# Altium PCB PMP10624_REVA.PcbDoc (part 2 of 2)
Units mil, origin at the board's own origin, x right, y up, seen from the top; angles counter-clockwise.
Board outline 2850 x 2600 mil, 4 copper layers (Top Layer, Signal Layer 1, Signal Layer 2, Bottom Layer), stack 61.2 mil thick; 108 components, 51 nets, 253 pads, 67 vias.
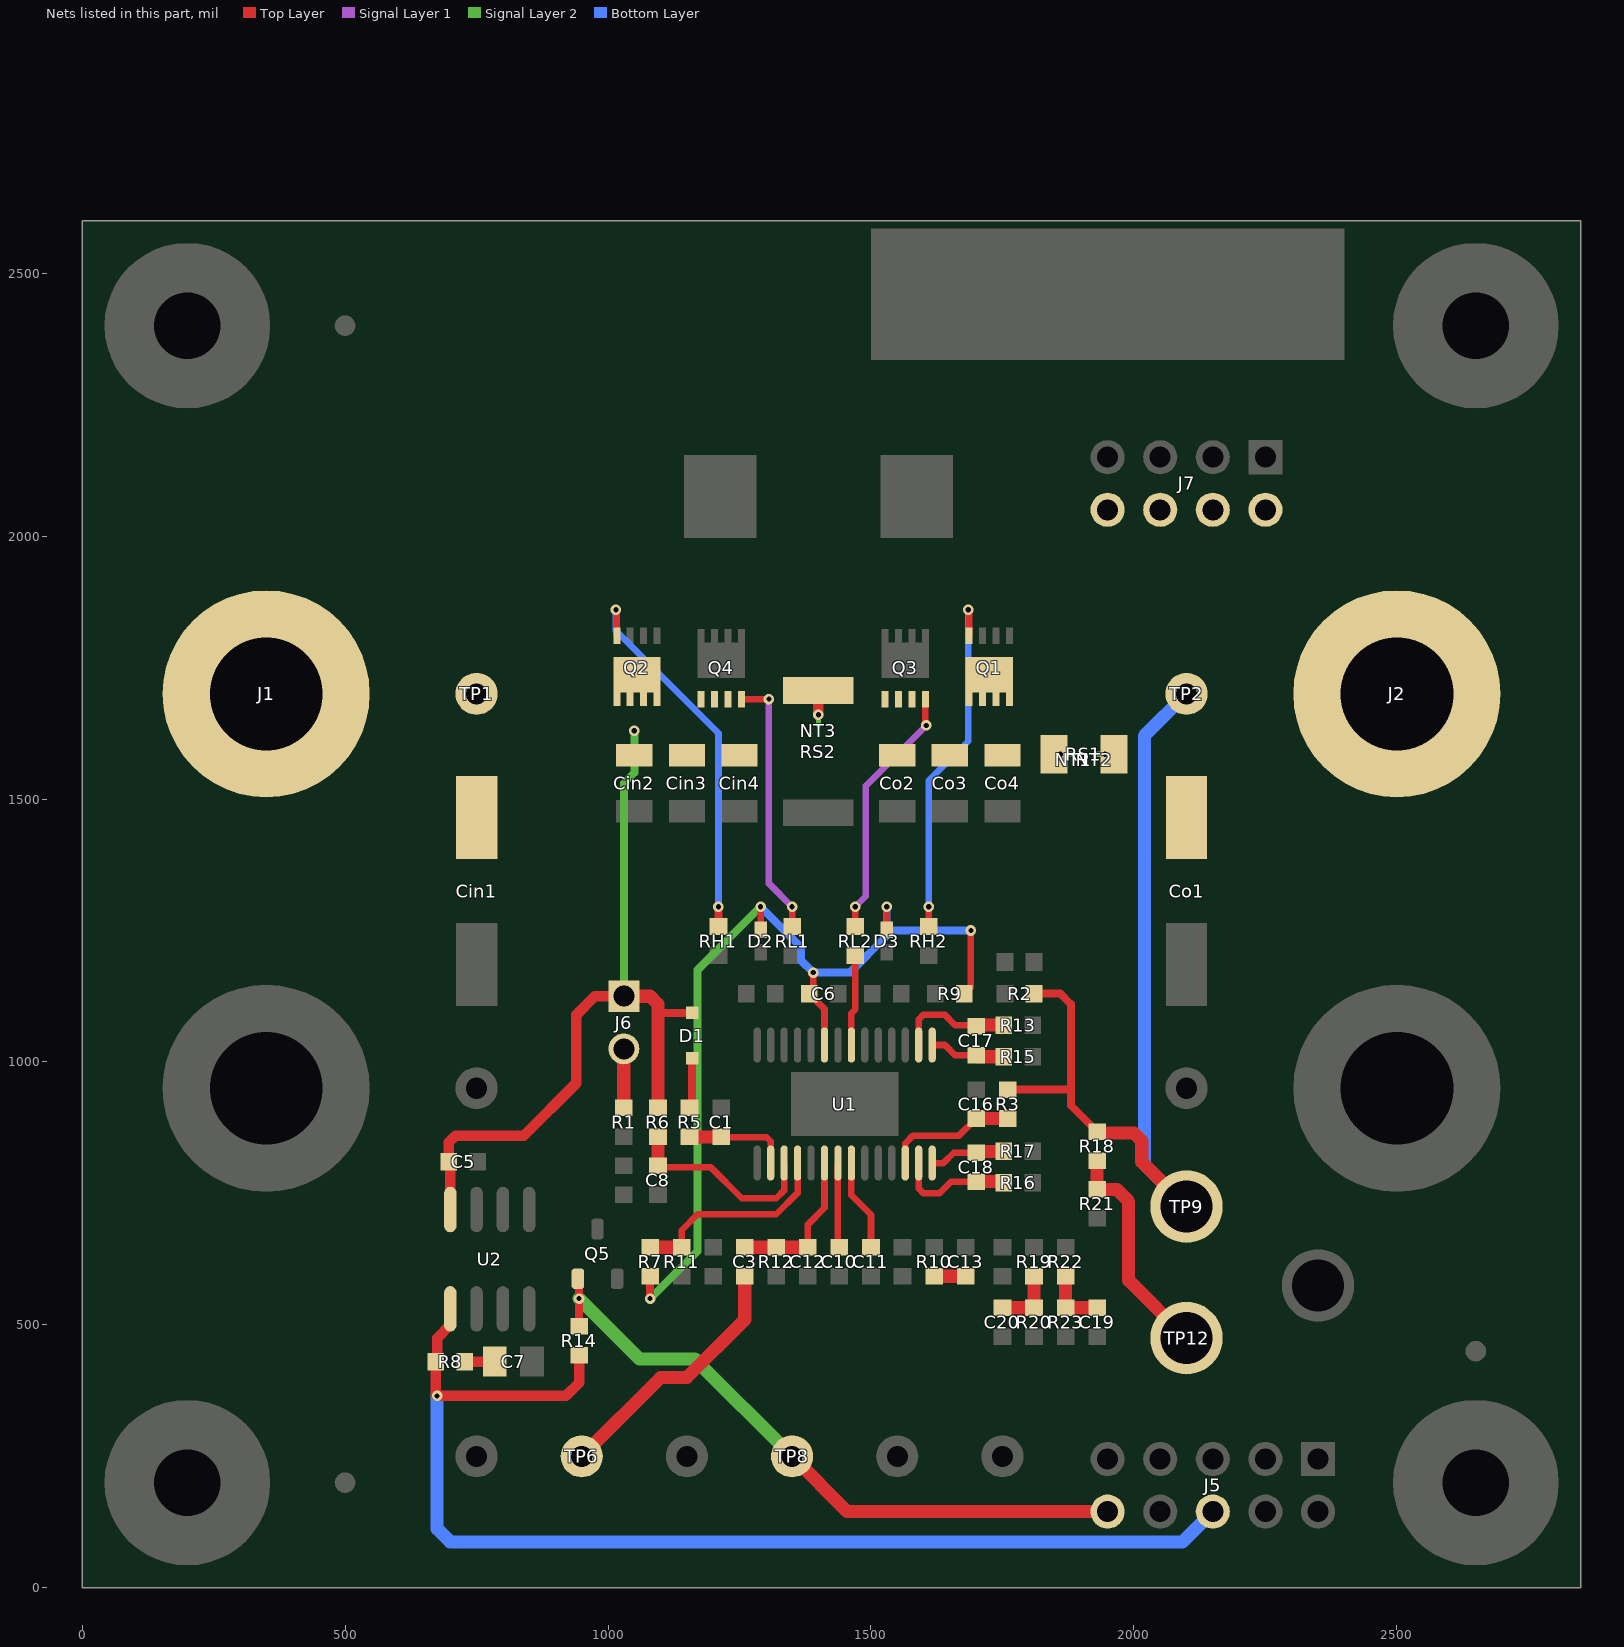
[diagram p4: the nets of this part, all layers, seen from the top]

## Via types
v1: diameter 20, hole 10, Top Layer to Bottom Layer, 59 vias
v2: diameter 40, hole 20, Top Layer to Bottom Layer, 8 vias

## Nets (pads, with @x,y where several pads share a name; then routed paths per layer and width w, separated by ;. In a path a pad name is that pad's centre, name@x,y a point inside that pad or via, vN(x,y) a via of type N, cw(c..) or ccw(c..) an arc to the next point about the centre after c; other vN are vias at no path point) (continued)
LDRV2: RL2.2 U1.21 | length 172.7
  Top Layer w12.5: U1.21@1462.8,1032.2 1462.8,1092.8 1470,1100 RL2.2@1470,1201.95
MODE: R7.1 R11.2 U1.4 | length 399.2
  Top Layer w12.5: R11.2@1140,647.56 1140,680 1170.37,710.37 1320,710.37 1360.43,750.81 U1.4@1360.43,807.8
  Top Layer w25: R7.1@1080,647.56 R11.2@1140,647.56
NetC3_1: C3.1 TP6.1 | length 500.1
  Top Layer w25: TP6.1@950,250 1100,400 1150,400 1260,510 C3.1@1260,592.44
NetC7_1: C7.1 R8.1 | length 57
  Top Layer w20: R8.1@727.56,430 C7.1@784.57,430
NetC13_1: C13.1 R10.1 | length 60
  Top Layer w25: R10.1@1620,592.44 C13.1@1680,592.44
NetC17_1: C17.1 R13.1 U1.16 | length 220.9
  Top Layer w12.5: U1.16@1590.75,1032.2 1590.75,1080.75 1600,1090 1640,1090 1660,1070 1697.56,1070 C17.1@1700,1067.56
  Top Layer w25: C17.1@1702.44,1070 R13.1@1752.44,1070
NetC17_2: C17.2 R15.1 U1.15 | length 145.3
  Top Layer w12.5: U1.15@1616.34,1032.2 1640.55,1032.2 1660.31,1012.44 C17.2@1700,1012.44
  Top Layer w25: C17.2@1700,1012.44 1702.44,1010 R15.1@1752.44,1010
NetC18_1: C18.1 R16.2 U1.13 | length 220.9
  Top Layer w12.5: U1.13@1590.75,807.8 1590.75,759.25 1600,750 1630,750 1652.44,772.44 C18.1@1700,772.44
  Top Layer w25: C18.1@1700,772.44 R16.2@1750,772.44
NetC18_2: C18.2 R17.2 U1.14 | length 145.3
  Top Layer w12.5: U1.14@1616.34,807.8 1637.8,807.8 1657.56,827.56 C18.2@1700,827.56
  Top Layer w25: C18.2@1700,827.56 1702.44,830 R17.2@1752.44,830
NetC19_1: C19.1 R22.1 R23.2 | length 119.9
  Top Layer w25: R22.1@1870,592.44 R23.2@1870,532.56 C19.1@1930,532.56
NetC20_1: C20.1 R19.1 R20.2 | length 119.9
  Top Layer w25: C20.1@1750,532.56 R20.2@1810,532.56 R19.1@1810,592.44
NetD1_1: D1.1 R5.2 | length 96.2
  Top Layer w15: R5.2@1155,912.56 1160,917.56 D1.1@1160,1006.69
NetJ6_2: J6.2 R1.2 | length 112.4
  Top Layer w25: R1.2@1030,912.56 J6.2@1030,1025
NetQ1_4: Q1.4 RH2.1 | length 683.6
  Top Layer w12.5: RH2.1@1610,1257.56 v1(1610,1295) ; v1(1685,1860) 1686.61,1858.39 Q1.4@1686.61,1810.53
  Bottom Layer w12.5: v1(1610,1295) 1610,1535 1685,1610 v1(1685,1860)
NetQ2_4: Q2.4 RH1.2 | length 733.3
  Top Layer w12.5: v1(1015,1860) 1016.61,1858.39 Q2.4@1016.61,1810.53
  Top Layer w15: RH1.2@1210,1257.56 v1(1210,1295)
  Bottom Layer w12.5: v1(1015,1860) 1015,1820 1210,1625 v1(1210,1295)
NetQ3_4: Q3.4 RL2.1 | length 488.5
  Top Layer w12.5: RL2.1@1470,1257.56 v1(1470,1295) ; Q3.4@1603.39,1689.47 1603.39,1641.61 v1(1605,1640)
  Signal Layer 1 w12.5: v1(1470,1295) 1490,1315 1490,1525 v1(1605,1640)
NetQ4_4: Q4.4 RL1.2 | length 503.4
  Top Layer w12.5: Q4.4@1253.39,1689.47 1305.33,1689.47 v1(1305.87,1690) ; RL1.2@1350,1257.56 v1(1350,1295)
  Signal Layer 1 w12.5: v1(1305.87,1690) 1305.87,1339.13 v1(1350,1295)
NetR18_2: R18.2 R21.2 TP12.1 | length 429.8
  Top Layer w25: R18.2@1930,812.44 R21.2@1930,757.56 1967.44,757.56 1990,735 1990,585 TP12.1@2100,475
SLOPE: C10.1 U1.7 | length 171.4
  Top Layer w12.5: C10.1@1437.2,640.35 U1.7@1437.2,807.8 ; C10.1@1437.2,650.35 C10.1@1440,647.56
SS: C11.1 U1.8 | length 175.6
  Top Layer w12.5: U1.8@1462.8,807.8 1462.8,746.68 1500,709.47 C11.1@1500,647.56
SYNC: C3.2 C12.2 R12.2 U1.6 | length 293.3
  Top Layer w12.5: C12.2@1380,647.56 1380,691.02 1411.61,722.64 U1.6@1411.61,807.8
  Top Layer w25: C3.2@1260,647.56 R12.2@1320,647.56 C12.2@1380,647.56
UFPBAR: J5.10 Q5.1 R14.1 TP8.1 | length 1260.6
  Top Layer w15: R14.1@945,497.56 v1(945,550) Q5.1@945,585.35
  Top Layer w25: TP8.1@1350,250 1455,145 J5.10@1950,145
  Signal Layer 2 w25: v1(945,550) 1060,435 1165,435 TP8.1@1350,250
VCC: C6.1 D2.2 D3.2 R7.2 R9.2 U1.23 | length 1784.7
  Top Layer w12.5: D2.2@1290,1251.65 v1(1290,1295) ; v1(1390,1170) 1390,1137.56 C6.1@1382.44,1130 1411.61,1100.83 U1.23@1411.61,1032.2 ; D3.2@1530,1251.65 v1@1530,1290 ; R9.2@1677.56,1130 1690,1142.44 v1(1690,1250)
  Top Layer w15: v1(1080,550) R7.2@1080,592.44
  Signal Layer 2 w15: v1(1080,550) 1170,640 1170,1175 v1(1290,1295)
  Bottom Layer w15: v1(1290,1295) 1366.85,1218.15 1366.85,1193.15 v1(1390,1170) 1460,1170 1530,1240 1530,1250 ; v1(1530,1295) 1530,1250 ; v1(1690,1250) 1530,1250
VDD: J5.6 R8.2 R14.2 U2.1 | length 2272.5
  Top Layer w20: U2.1@700,530.51 700,500 675,475 675,432.56 R8.2@672.44,430 672.44,367.56 v1(675,365) 920,365 945,390 R14.2@945,442.44
  Bottom Layer w25: v1(675,365) 675,112.5 700,87.5 2092.5,87.5 J5.6@2150,145
VIN: C5.1 Cin1.1 Cin2.1 Cin3.1 Cin4.1 D1.2 J1.1 J6.1 Q2.5 Q2.6 Q2.7 Q2.8 Q2.9 R6.1 TP1.1 U2.8 | length 1500.3
  Top Layer w15: 1095,1095 1096.69,1093.31 D1.2@1160,1093.31
  Top Layer w20: U2.8@700,719.49 700,807.44 C5.1@697.44,810 697.44,847.44 710,860 840,860 940,960 940,1090 975,1125 J6.1@1030,1125
  Top Layer w25: J6.1@1030,1125 1080,1125 1095,1110 1095,1095 R6.1@1095,912.56
  Signal Layer 2 w15: J6.1@1030,1125 1030,1530 1050,1550 v1(1050,1630)
VIN_IC: C1.1 R5.1 U1.2 | length 199.1
  Top Layer w12.5: C1.1@1215,857.44 1215.43,857.01 1301.5,857.01 1309.25,849.25 U1.2@1309.25,807.8
  Top Layer w25: R5.1@1155,857.44 C1.1@1215,857.44
VINSNS: C8.2 R6.2 U1.3 | length 378.7
  Top Layer w12.5: C8.2@1095,802.56 1097.56,800 1195,800 1254.25,740.75 1320,740.75 1334.84,755.59 U1.3@1334.84,807.8
  Top Layer w25: C8.2@1095,802.56 R6.2@1095,857.44
VOSNS: C16.1 R3.1 U1.12 | length 251.8
  Top Layer w12.5: U1.12@1565.16,807.8 1565.16,845.16 1580,860 1667.56,860 C16.1@1700,892.44
  Top Layer w25: C16.1@1700,892.44 R3.1@1760,892.44
VOUT: Co1.1 J2.1 J7.2 J7.4 J7.6 J7.8 NT2.2 R2.2 R3.2 R18.1 RS1.2 TP2.1 TP9.1 | length 1776.2
  Top Layer w15: R3.2@1760,947.56 1877.56,947.56 1880,950 ; R2.2@1810,1130 1860,1130 1880,1110 1880,950 ; R18.1@1930,867.56 1880,917.56 1880,950
  Top Layer w25: R18.1@1930,867.56 1932.56,865 2000,865 2015,850 2015,810 TP9.1@2100,725
  Signal Layer 2 w10: NT2.2@1925,1585 v1(1945,1585)
  Bottom Layer w25: TP9.1@2100,725 2020,805 2020,1620 TP2.1@2100,1700
VOUTC: Co2.1 Co3.1 Co4.1 NT1.2 Q1.5 Q1.6 Q1.7 Q1.8 Q1.9 RS1.1 | length 25
  Signal Layer 2 w10: v1(1860,1585) NT1.2@1885,1585
VRS: NT3.1 Q3.1 Q3.2 Q3.3 Q4.1 Q4.2 Q4.3 RS2.2 | length 66.1
  Top Layer w20: v1(1400,1660) RS2.2@1400,1706.14
  Signal Layer 2 w10: NT3.1@1400,1640 v1(1400,1660)
pads on no net: FID1.1 FID2.1 FID3.1 H1.1 H2.1 H3.1 H4.1 Logo1.0 U2.4 U2.5

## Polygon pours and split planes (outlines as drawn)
GND on Signal Layer 2 "Signal Layer 2-GND" (solid, remove dead copper, pour order 50): 0,0 0,2600 2850,2600 2850,0
GND on Signal Layer 1 "Signal Layer 1-GND" (solid, remove dead copper, pour order 49): 0,0 0,2600 2850,2600 2850,0
VIN on Bottom Layer "Bottom Layer-VIN" (solid, remove dead copper, pour order 51): 0,2100 1100,2100 1100,1360 510,1360 0,1360
VOUT on Bottom Layer "Top Layer-VOUT" (solid, remove dead copper, pour order 52): 1910,1650 1910,2100 2850,2100 2850,1330 2000,1330 2000,1650
GND on Bottom Layer "Bottom Layer-GND" (solid, remove dead copper, pour order 54): 0,0 0,2600 2850,2600 2850,0
VOUT on Top Layer "Top Layer-VOUT" (solid, remove dead copper, pour order 44): 1910,1330 1910,2100 2850,2100 2850,1940 2850,1330
VOUTC on Top Layer "Top Layer-VOUTC" (solid, remove dead copper, pour order 43): 1480,1610 1650,1610 1650,1770 1900,1770 1900,1535 1480,1535
VIN on Top Layer "Top Layer-VIN" (solid, remove dead copper, pour order 40): 0,2100 1000,2100 1000,1770 1130,1770 1130,1610 1320,1610 1320,1535 1000,1535 900,1535 900,1330 0,1330
GND on Top Layer "Top Layer-GND" (solid, remove dead copper, pour order 48): 0,0 0,2600 2850,2600 2850,0
VRS on Top Layer "Top Layer-VRS" (solid, remove dead copper, pour order 11): 1235,1710 1235,1662.6 1325,1662.6 1325,1755 1475,1755 1475,1710 1585,1710 1585,1620 1140,1620 1140,1710
HDRV1_N on Top Layer "Top Layer-SW1" (solid, remove dead copper, pour order 13): 1035,1790 1035,2185 1310,2185 1310,1725 1140,1725 1140,1790
HDRV2_N on Top Layer "Top Layer-SW2" (solid, remove dead copper, pour order 15): 1490,1725 1490,2185 1800,2185 1800,1790 1705,1790 1705,1885 1640,1885 1640,1725 1500,1725

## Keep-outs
Keep-Out Layer:
  lines w10: 6390,-5 ccw(c6390,0) 6395,0 ; -5,0 ccw(c0,0) 0,-5 ; -5,0 ccw(c0,0) 0,-5 ; -5,0 -5,2600 ; -5,2600 cw(c0,2600) 0,2605 ; -5,2600 cw(c0,2600) 0,2605 ; 0,-5 2850,-5 ccw(c2850,0) 2855,0 2855,2600 ; 0,2605 2850,2605 ; 2850,2605 cw(c2850,2600) 2855,2600 ; 2850,2605 cw(c2850,2600) 2855,2600
  text ".Layer_Name" at 577,-858.49 h60

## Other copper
Top Layer:
  text ".CopyrightYear" at 165,415 h60
  text "TI" at 441,415 h60
  text "©" at 48,411.48 h105
  text ".Layer_Name" at 577,-858.49 h60
Bottom Layer:
  text ".VersionControl_RevNumber" at 2590,2660 h60
  text "SVN:" at 2850,2660 h60
  text "MADE IN U.S." at 1365,120 h60
  text "UL94V-0" at 1880,120 h60
  text ".Layer_Name" at 577,-858.49 h60

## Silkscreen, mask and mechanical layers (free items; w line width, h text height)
Top Overlay:
  text "LM5175 Buck/Boost" at 450,2490 h60
  text ".PRJ_Number" at 675,2365 h60
  text ".PCB_Rev" at 1215,2365 h60
  text ".Layer_Name" at 577,-858.49 h60
Bottom Overlay:
  text ".Layer_Name" at 577,-858.49 h60
Top Paste:
  text ".Layer_Name" at 577,-858.49 h60
Bottom Paste:
  text ".Layer_Name" at 577,-858.49 h60
Top Solder:
  text ".Layer_Name" at 577,-858.49 h60
  text ".Layer_Name" at 577,-858.49 h60
Bottom Solder:
  text ".Layer_Name" at 577,-858.49 h60
Drill Guide:
  text ".Layer_Name" at 577,-858.49 h60
M1 Board Outline:
  the board outline again, w10
  text ".Layer_Name" at 577,-858.49 h60
M2 Board Dimensions:
  rectangle: 0,-275 125,-150
  rectangle: 125,-400 500,-275
  lines w7: 0,-275 1000,-275 ; 125,-400 125,-150 ; 250,-400 250,-150 ; 500,-400 500,-150 ; 750,-400 750,-150 ; 0,-400 1000,-400 1000,-150 0,-150 0,-400
  text ".Layer_Name" at 577,-858.49 h60
M3 3D STEP Top:
  text ".Layer_Name" at 577,-858.49 h60
M4 3D STEP Bottom:
  text ".Layer_Name" at 577,-858.49 h60
M5 Assembly Top:
  lines w10: -292,-930.17 6308,-930.17 ; -292,-726.83 6310,-726.83 ; -292,-523.5 -292,-1133.5 3713,-1133.5 6310,-1133.5 6310,-523.5 -291.5,-523.5 -291.5,-1133.5 1284,-1133.5 ; 2173,-1133.5 2173,-523.5 ; 3440,-726.83 3440,-523.5 ; 4280,-726.83 4280,-523.5 ; 4902,-1140 4902,-937.17
  text "COMPONENTS MARKED 'DNP' SHOULD NOT BE POPULATED." at 1153.5,-318.5 h60
  text "ASSEMBLY VARIANT:" at 1153,-434 h60
  text ".VariantName" at 2189,-434 h60
  text "PCB VIEWED FROM TOP SIDE" at -228.5,-655.67 h60
  text "BOARD #:" at 2248,-655.67 h60
  text ".PRJ_Number" at 2793.5,-655.67 h60
  text "REV:" at 3638,-655.67 h60
  text ".PCB_Rev" at 3929.5,-655.67 h60
  text "SVN REV:" at 4476,-655.67 h60
  text ".VersionControl_RevNumber" at 4982,-655.67 h60
  text "PLOT NAME =" at -228.5,-1064.34 h60
  text ".plot_File_Name" at 577,-1064.34 h60
  text "GENERATED    :" at 2250,-1064.34 h60
  text ".Print_Date" at 3119.5,-1064.34 h60
  text ".Print_Time" at 3848.5,-1064.34 h60
  text "TEXAS INSTRUMENTS" at 5113,-1064.34 h60
M6 Assembly Bottom:
  lines w10: -292.5,-727.33 6309.5,-727.33 ; -290.5,-930.67 6309.5,-930.67 ; 1115.5,-1140.5 1115.5,-937.67 ; 1737.5,-727.33 1737.5,-524 ; 2577.5,-727.33 2577.5,-524 ; 3844.5,-1134 3844.5,-524 ; 4733.5,-1134 6309,-1134 6309,-524 -292.5,-524 -292.5,-1134 2304.5,-1134 6309.5,-1134 6309.5,-524
  text "COMPONENTS MARKED 'DNP' SHOULD NOT BE POPULATED." at 6102,-318 h60
  text ".VariantName" at 5058,-434 h60
  text "ASSEMBLY VARIANT:" at 6097,-434 h60
  text ".VersionControl_RevNumber" at 1035.5,-656.17 h60
  text "SVN REV:" at 1541.5,-656.17 h60
  text ".PCB_Rev" at 2088,-656.17 h60
  text "REV:" at 2379.5,-656.17 h60
  text ".PRJ_Number" at 3224,-656.17 h60
  text "BOARD #:" at 3769.5,-656.17 h60
  text "PCB VIEWED FROM BOTTOM SIDE" at 6246,-656.17 h60
  text "TEXAS INSTRUMENTS" at 904.5,-1064.84 h60
  text ".Print_Time" at 2169,-1064.84 h60
  text ".Print_Date" at 2898,-1064.84 h60
  text "GENERATED    :" at 3767.5,-1064.84 h60
  text ".plot_File_Name" at 5440.5,-1064.84 h60
  text "PLOT NAME =" at 6246,-1064.84 h60
M9 Title Sheet:
  drawing of 57 lines, arcs and shapes, not listed
  text "1" at 739.84,8036.5 h70
  text "2" at 3235.5,8036.5 h70
  text "3" at 5724.84,8036.5 h70
  text "4" at 8231.51,8036.5 h70
  text "5" at 10730.5,8036.5 h70
  text "6" at 13235.5,8036.5 h70
  text "A" at -416.5,6893.5 h70
  text "A" at 14383.5,6893.5 h70
  text "B" at -416.5,4513.5 h70
  text "B" at 14383.5,4513.5 h70
  text "C" at -416.5,2138.5 h70
  text "C" at 14383.5,2138.5 h70
  text "PROJECT TITLE:" at 11343.5,277.5 h45
  text ".PRJ_Title" at 11393.5,144.17 h70
  text "DESIGNED FOR:" at 11343.5,-23.5 h45
  text ".PRJ_Customer" at 11393.5,-163.5 h70
  text "D" at -416.5,-231.5 h70
  text "D" at 14383.5,-231.5 h70
  text "FILE NAME:" at 11343.5,-323.5 h45
  text ".PCB_File_Name_No_Path" at 11393.5,-443.5 h70
  text "Texas Instruments (TI) and/or its licensors do not warrant the accuracy or completeness of this specification" at 6374,-605.34 h45
  text "ENGINEER:" at 11343.5,-613.5 h45
  text "LAYOUT BY:" at 12848.5,-613.5 h45
  text "or any information contained therein. TI and/or its licensors do not warrant that this design will meet" at 6329.01,-718 h45
  text ".PRJ_Engineer" at 11393.5,-768.49 h70
  text ".PCB_Layout" at 12899,-768.49 h70
  text "the specifications, will be suitable for your application or fit for any particular purpose, or will operate in" at 6329.01,-830.67 h45
  text ".Layer_Name" at 577,-858.49 h60
  text "ALTIUM DESIGNER VERSION:" at 12848.5,-923.5 h45
  text "an implementation. TI and/or its licensors do not warrant that the design is production worthy. You should" at 6329.01,-943.33 h45
  text "completely validate and test your design implementation to confirm the system functionality for your application." at 6374,-1056 h45
  text ".print_Scale" at 11393.5,-1056.83 h70
  text ".Application_BuildNumber" at 12899,-1056.83 h70
  text "1" at 739.84,-1263.5 h70
  text "2" at 3235.5,-1263.5 h70
  text "3" at 5724.84,-1263.5 h70
  text "4" at 8231.51,-1263.5 h70
  text "5" at 10730.5,-1263.5 h70
  text "6" at 13235.5,-1263.5 h70
M10 Fab Notes:
  drawing of 185 lines, arcs and shapes, not listed
  text "DESIGN INFORMATION" at 12381.02,5910 h60
  text "MIN. TRACK WIDTH:" at 11736.46,5730 h60
  text "7.8" at 12775,5730 h60
  text "MIL" at 12987.46,5730 h60
  text "MIN. CLEARANCE:" at 11736.46,5598 h60
  text "0.2" at 12772.7,5598 h60
  text "mm" at 12987.46,5598 h60
  text "MIN. VIA PAD SIZE:" at 11736.46,5466 h60
  text "20" at 12802.71,5466 h60
  text "MIL" at 12987.46,5466 h60
  text "0.05mm (2MIL)" at 12431.46,5324.29 h60
  text "MINIMUM ANNULAR RING" at 11407.23,5320 h60
  text "EXTERNAL" at 13139.46,5320 h60
  text "PER" at 11607.23,5202 h60
  text "IPC-D-275 CLASS 2 LEVEL C" at 11827.23,5202 h60
  text "MIL, HOLES" at 13315.46,5089.71 h60
  text "+/-" at 12923,5089 h60
  text "+/-" at 13777,5089 h60
  text "REGISTRATION TOLERANCES:" at 11407.23,5084 h60
  text "METAL" at 12607,5084 h60
  text "5" at 13183.2,5084 h60
  text "3" at 14016.2,5084 h60
  text "MIL" at 14132.46,5084 h60
  text "MATERIAL:" at 11332.46,4874.54 h60
  text "FR-4 High Tg" at 12318.9,4734.21 h60
  text "FR-408" at 11753.46,4725.64 h60
  text "OTHER" at 13241.46,4725.64 h60
  text "X" at 11600,4720 h60
  text "62 MIL (1.6mm) +/-10%" at 12073.56,4562.92 h60
  text "THICKNESS:" at 11407.23,4558.64 h60
  text "X" at 11945.4,4558.64 h60
  text "OTHER" at 13358.46,4558.64 h60
  text "TOLERANCE:" at 11407.23,4400.64 h60
  text "X" at 12246.53,4400.64 h60
  text "ANSI IPC-6012 TYPE 3 CLASS 2" at 12433.48,4400.64 h60
  text "OTHER +/-" at 12433.46,4244.64 h60
  text "BOW & TWIST:" at 11407.23,4087.64 h60
  text "X" at 12246.53,4087.64 h60
  text "ANSI IPC-6012 TYPE 3 CLASS 2" at 12433.48,4087.64 h60
  text "OTHER +/-" at 12433.46,3929.13 h60
  text "DRILLING:" at 11332.46,3790.64 h60
  text "REFERENCE:" at 11407.23,3673.64 h60
  text "X" at 12055.46,3673.64 h60
  text "AS SHOWN" at 12242.46,3673.64 h60
  text "X" at 12956.46,3673.64 h60
  text "NC_DRILL FILES" at 13093.46,3673.64 h60
  text "PTH MIN COPPER THICKNESS:" at 11407.23,3515.64 h60
  text "X" at 12757.46,3515.64 h60
  text "1MIL" at 12894.46,3515.64 h60
  text "OTHER" at 13391.46,3515.64 h60
  text "BOARD FINISH:" at 11332.46,3356.64 h60
  text "SILKSCREEN:" at 11487.68,3238.64 h60
  text "X" at 12436.46,3238.64 h60
  text "TOP" at 12562.46,3238.64 h60
  text "X" at 12946.46,3238.64 h60
  text "BOTTOM" at 13073.46,3238.64 h60
  text "SILKSCREEN COLOR:" at 11487.68,3071.64 h60
  text "X" at 12435.42,3071.64 h60
  text "WHITE" at 12562.46,3071.64 h60
  text "OTHER" at 13073.46,3071.64 h60
  text "SOLDER RESIST COLOR:" at 11487.68,2901.64 h60
  text "X" at 12055.42,2742.44 h60
  text "GREEN" at 12182.46,2742.44 h60
  text "BLUE" at 12773.46,2742.44 h60
  text "OTHER" at 13311.46,2742.44 h60
  text "IMMERSION GOLD (ENIG)" at 12393.46,2553.92 h60
  text "ENEPIG" at 13731,2550.64 h60
  text "SURFACE FINISH:" at 11332.46,2549.64 h60
  text "IMM. TIN/SILVER OR EQUIV" at 11662,2392.64 h60
  text "OTHER" at 13093.46,2392.64 h60
  text "X" at 11500,2385 h60
  text "ARRAY/PANEL:" at 11332.46,2213.64 h60
  text "X" at 12205,2210 h60
  text "CUT AND TRIM PER MECH LAYER 1" at 12393.46,2209.35 h60
  text "N.C. ROUTE" at 12393.46,2057.64 h60
  text "V. SCORE" at 13259.46,2057.64 h60
  text "CERTIFICATION:" at 11332.46,1920.64 h60
  text "MATERIALS AND WORKMANSHIP FOR ALL PCBS" at 12057.46,1920.64 h60
  text "TO MEET OR EXCEED THE REQUIREMENTS OF:" at 12057.46,1822.64 h60
  text "X" at 11683.96,1686.13 h60
  text "ANSI IPC-A-600F CLASS ->" at 11822.96,1686.13 h60
  text "X" at 13462.02,1686.13 h60
  text "2" at 13580.96,1686.14 h60
  text "1" at 13265.96,1684.64 h60
  text "3" at 13934.96,1684.64 h60
  text "X" at 11686.02,1526.64 h60
  text "UL 94V-0" at 11822.96,1526.64 h60
  text "X" at 12498.02,1526.64 h60
  text "RoHS" at 12634.96,1526.64 h60
  text "OTHER" at 13279.36,1526.64 h60
  text "PER ORDER" at 13676.42,1526.64 h60
  text "ADDITIONAL REQUIREMENTS:" at 11332.46,1385.64 h60
  text "MICROSECTION:" at 11407.23,1270.64 h60
  text "YES" at 12312.96,1270.64 h60
  text "REQUIRED" at 13174.46,1114.49 h60
  text "BARE BOARD ELEC. TEST:" at 11407.23,1111.64 h60
  text "NONE" at 12712.96,1111.64 h60
  text "PER ORDER" at 13766.46,1111.64 h60
  text "X" at 13640,1110 h60
  text "MANUFACTURER'S UL:" at 11407.23,954.64 h60
  text "RAIL" at 12572.96,950.35 h60
  text "METAL" at 13064.77,950.35 h60
  text "X" at 13440,950 h60
  text "SILK" at 13576.46,950.35 h60
  text ".Layer_Name" at 577,-858.49 h60
M11 Gerber Information:
  lines w10: -292,-930.17 6308,-930.17 ; -292,-726.83 6310,-726.83 ; -292,-523.5 -292,-1133.5 3713,-1133.5 6310,-1133.5 6310,-523.5 -291.5,-523.5 -291.5,-1133.5 1284,-1133.5 ; 2173,-1133.5 2173,-523.5 ; 3440,-726.83 3440,-523.5 ; 4280,-726.83 4280,-523.5 ; 4902,-1140 4902,-937.17
  text "ALL ARTWORK VIEWED FROM TOP SIDE" at -228.5,-655.67 h60
  text "BOARD #:" at 2248,-655.67 h60
  text ".PRJ_Number" at 2793.5,-655.67 h60
  text "REV:" at 3638,-655.67 h60
  text ".PCB_Rev" at 3929.5,-655.67 h60
  text "SVN REV:" at 4476,-655.67 h60
  text ".VersionControl_RevNumber" at 4982,-655.67 h60
  text "LAYER NAME =" at -228.5,-858.49 h60
  text "PLOT NAME =" at -228.5,-1064.34 h60
  text ".plot_File_Name" at 577,-1064.34 h60
  text "GENERATED    :" at 2250,-1064.34 h60
  text ".Print_Date" at 3119.5,-1064.34 h60
  text ".Print_Time" at 3848.5,-1064.34 h60
  text "TEXAS INSTRUMENTS" at 5113,-1064.34 h60
M12 Stackup:
  drawing of 295 lines, arcs and shapes, not listed
  text "Layer" at 9605.74,7700 h60
  text "Name" at 10015.66,7700 h60
  text "Material" at 10955.4,7700 h60
  text "Thickness" at 11815.16,7700 h60
  text "Constant" at 12465,7700 h60
  text "Board Layer Stack" at 13034.86,7700 h60
  text "1" at 9605.74,7580 h60
  text "Top Overlay" at 10015.66,7580 h60
  text "2" at 9605.74,7460 h60
  text "Top Solder" at 10015.66,7460 h60
  text "Solder Resist" at 10955.4,7460 h60
  text "0.40mil" at 11815.16,7460 h60
  text "3.5" at 12465,7460 h60
  text "3" at 9605.74,7340 h60
  text "Top Layer" at 10015.66,7340 h60
  text "Copper" at 10955.4,7340 h60
  text "2.80mil" at 11815.16,7340 h60
  text "4" at 9605.74,7220 h60
  text "Dielectric1" at 10015.66,7220 h60
  text "FR-4" at 10955.4,7220 h60
  text "20.00mil" at 11815.16,7220 h60
  text "4.8" at 12465,7220 h60
  text "5" at 9605.74,7100 h60
  text "Signal Layer 1" at 10015.66,7100 h60
  text "Copper" at 10955.4,7100 h60
  text "1.40mil" at 11815.16,7100 h60
  text "6" at 9605.74,6980 h60
  text "Dielectric 2" at 10015.66,6980 h60
  text "12.80mil" at 11815.16,6980 h60
  text "4.2" at 12465,6980 h60
  text "7" at 9605.74,6860 h60
  text "Signal Layer 2" at 10015.66,6860 h60
  text "Copper" at 10955.4,6860 h60
  text "1.40mil" at 11815.16,6860 h60
  text "8" at 9605.74,6740 h60
  text "Dielectric 3" at 10015.66,6740 h60
  text "FR-4" at 10955.4,6740 h60
  text "20.00mil" at 11815.16,6740 h60
  text "4.8" at 12465,6740 h60
  text "9" at 9605.74,6620 h60
  text "Bottom Layer" at 10015.66,6620 h60
  text "Copper" at 10955.4,6620 h60
  text "2.80mil" at 11815.16,6620 h60
  text "10" at 9605.74,6500 h60
  text "Bottom Solder" at 10015.66,6500 h60
  text "Solder Resist" at 10955.4,6500 h60
  text "0.40mil" at 11815.16,6500 h60
  text "3.5" at 12465,6500 h60
  text "11" at 9605.74,6380 h60
  text "Bottom Overlay" at 10015.66,6380 h60
  text ".Layer_Name" at 577,-858.49 h60
M13 Component Bodies Top:
  text ".Layer_Name" at 577,-858.49 h60
M14 Component Bodies Bottom:
  text ".Layer_Name" at 577,-858.49 h60
M15 Courtyards Top:
  text ".Layer_Name" at 577,-858.49 h60
M16 Courtyards Bottom:
  text ".Layer_Name" at 577,-858.49 h60
Drill Drawing:
  circle w3.33: c3592.72,1923.08 r24.89
  lines w3.33: 3567.83,1599.56 3617.6,1599.56 3617.6,1649.33 3567.83,1649.33 3567.83,1599.56 ; 3567.83,1748.88 3617.6,1748.88 3617.6,1798.65 3567.83,1798.65 3567.83,1748.88 ; 3567.83,2047.52 3592.72,2059.96 3617.6,2047.52 3605.16,2072.4 3617.6,2097.29 3592.72,2084.85 3567.83,2097.29 3580.27,2072.4 3567.83,2047.52 ; 3567.83,2246.61 3617.6,2246.61 3592.72,2196.84 3567.83,2246.61 ; 3567.83,2371.04 3592.72,2346.16 3617.6,2371.04 3592.72,2395.93 3567.83,2371.04 ; 3577.78,1609.51 3607.65,1609.51 3607.65,1639.37 3577.78,1639.37 3577.78,1609.51
  lines w12: 3500,1554.76 5618.02,1554.76 ; 3500,2450.68 5618.02,2450.68 ; 3870.36,1405.44 3870.36,2600 ; 4227.36,1405.44 4227.36,2600 ; 4888.93,1405.44 4888.93,2600 ; 5173.07,1405.44 5173.07,2600 ; 3500,1405.44 5618.02,1405.44 5618.02,2600 3500,2600 3500,1405.44
  text "Symbol" at 3589.59,2495.48 h72
  text "Quantity" at 3915.16,2495.48 h72
  text "Finished Hole Size" at 4272.16,2495.48 h72
  text "Plated" at 4933.72,2495.48 h72
  text "Hole Type" at 5217.86,2495.48 h72
  text "59" at 3915.16,2346.16 h60
  text "10.00mil (0.254mm)" at 4272.16,2346.16 h60
  text "PTH" at 4933.72,2346.16 h60
  text "Round" at 5217.86,2346.16 h60
  text "8" at 3915.16,2196.84 h60
  text "20.00mil (0.508mm)" at 4272.16,2196.84 h60
  text "PTH" at 4933.72,2196.84 h60
  text "Round" at 5217.86,2196.84 h60
  text "30" at 3915.16,2047.52 h60
  text "40.00mil (1.016mm)" at 4272.16,2047.52 h60
  text "PTH" at 4933.72,2047.52 h60
  text "Round" at 5217.86,2047.52 h60
  text "3" at 3915.16,1898.2 h60
  text "98.43mil (2.500mm)" at 4272.16,1898.2 h60
  text "PTH" at 4933.72,1898.2 h60
  text "Round" at 5217.86,1898.2 h60
  text "4" at 3915.16,1748.88 h60
  text "125.98mil (3.200mm)" at 4272.16,1748.88 h60
  text "PTH" at 4933.72,1748.88 h60
  text "Round" at 5217.86,1748.88 h60
  text "4" at 3915.16,1599.56 h60
  text "214.57mil (5.450mm)" at 4272.16,1599.56 h60
  text "PTH" at 4933.72,1599.56 h60
  text "Round" at 5217.86,1599.56 h60
  text "108 Total" at 3915.16,1450.24 h60
  text ".Layer_Name" at 577,-858.49 h60

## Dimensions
0,-400 to 1000,-400 on M2 Board Dimensions
0,2600 to 0,0 on M2 Board Dimensions
2850,0 to 0,0 on M2 Board Dimensions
